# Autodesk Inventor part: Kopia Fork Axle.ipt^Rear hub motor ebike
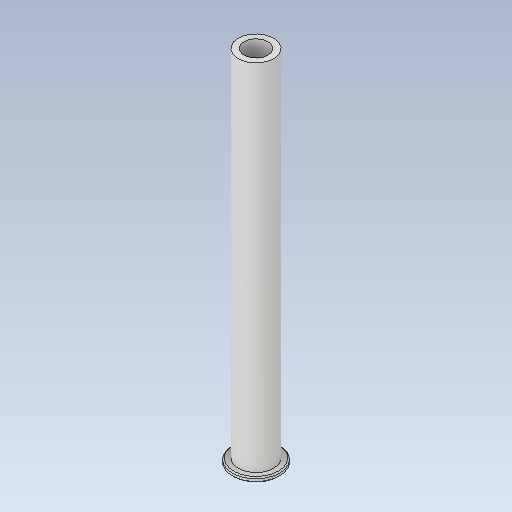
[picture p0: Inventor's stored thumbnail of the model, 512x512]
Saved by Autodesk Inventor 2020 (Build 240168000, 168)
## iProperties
Created: 2017-11
Part Number: Kopia Fork Axle.ipt^Rear hub motor ebike
Material: Ogólny
Document SubType Name: Modeling
Designer: Tomasz
Density: 1 g/cm^3
Appearance: Domyślna
Sending System: SolidWorks 2017
Last Author: Tomasz
Last Saved: 2017-11-19
Author: Tomasz
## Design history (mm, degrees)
feature "Fork Axle.ipt"
node "Bryła1"
